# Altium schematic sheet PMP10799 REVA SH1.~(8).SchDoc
size 431 x 279 mm; Date: Not shown in title block; ApprovedBy: Not shown in title block; CheckedBy: Not shown in title block; Author: Not shown in title block; CompanyName: Not shown in title block; Engineer: Not shown in title block; Organization: Not shown in title block; Address1: Not shown in title block; Address2: Not shown in title block; Address3: Not shown in title block; Address4: Not shown in title block; DocumentNumber: 1; Revision: Use project parameter SCH_Rev; SheetNumber: 1; SheetTotal: 2; PageSetup: Record=PageOptions¦CenterHorizontal=True¦CenterVertical=True¦PrintScale=1.00¦XCorrection=1.00¦YCorrection=1.00¦PrintKind=0¦BorderSize=5000000¦LeftOffset=0¦BottomOffset=0¦Orientation=2¦PaperLength=1000¦PaperWidth=1000¦Scale=100¦PaperSource=15¦PrintQuality=600¦MediaType=1¦DitherType=10¦PaperKind=Letter¦PrintScaleMode=1
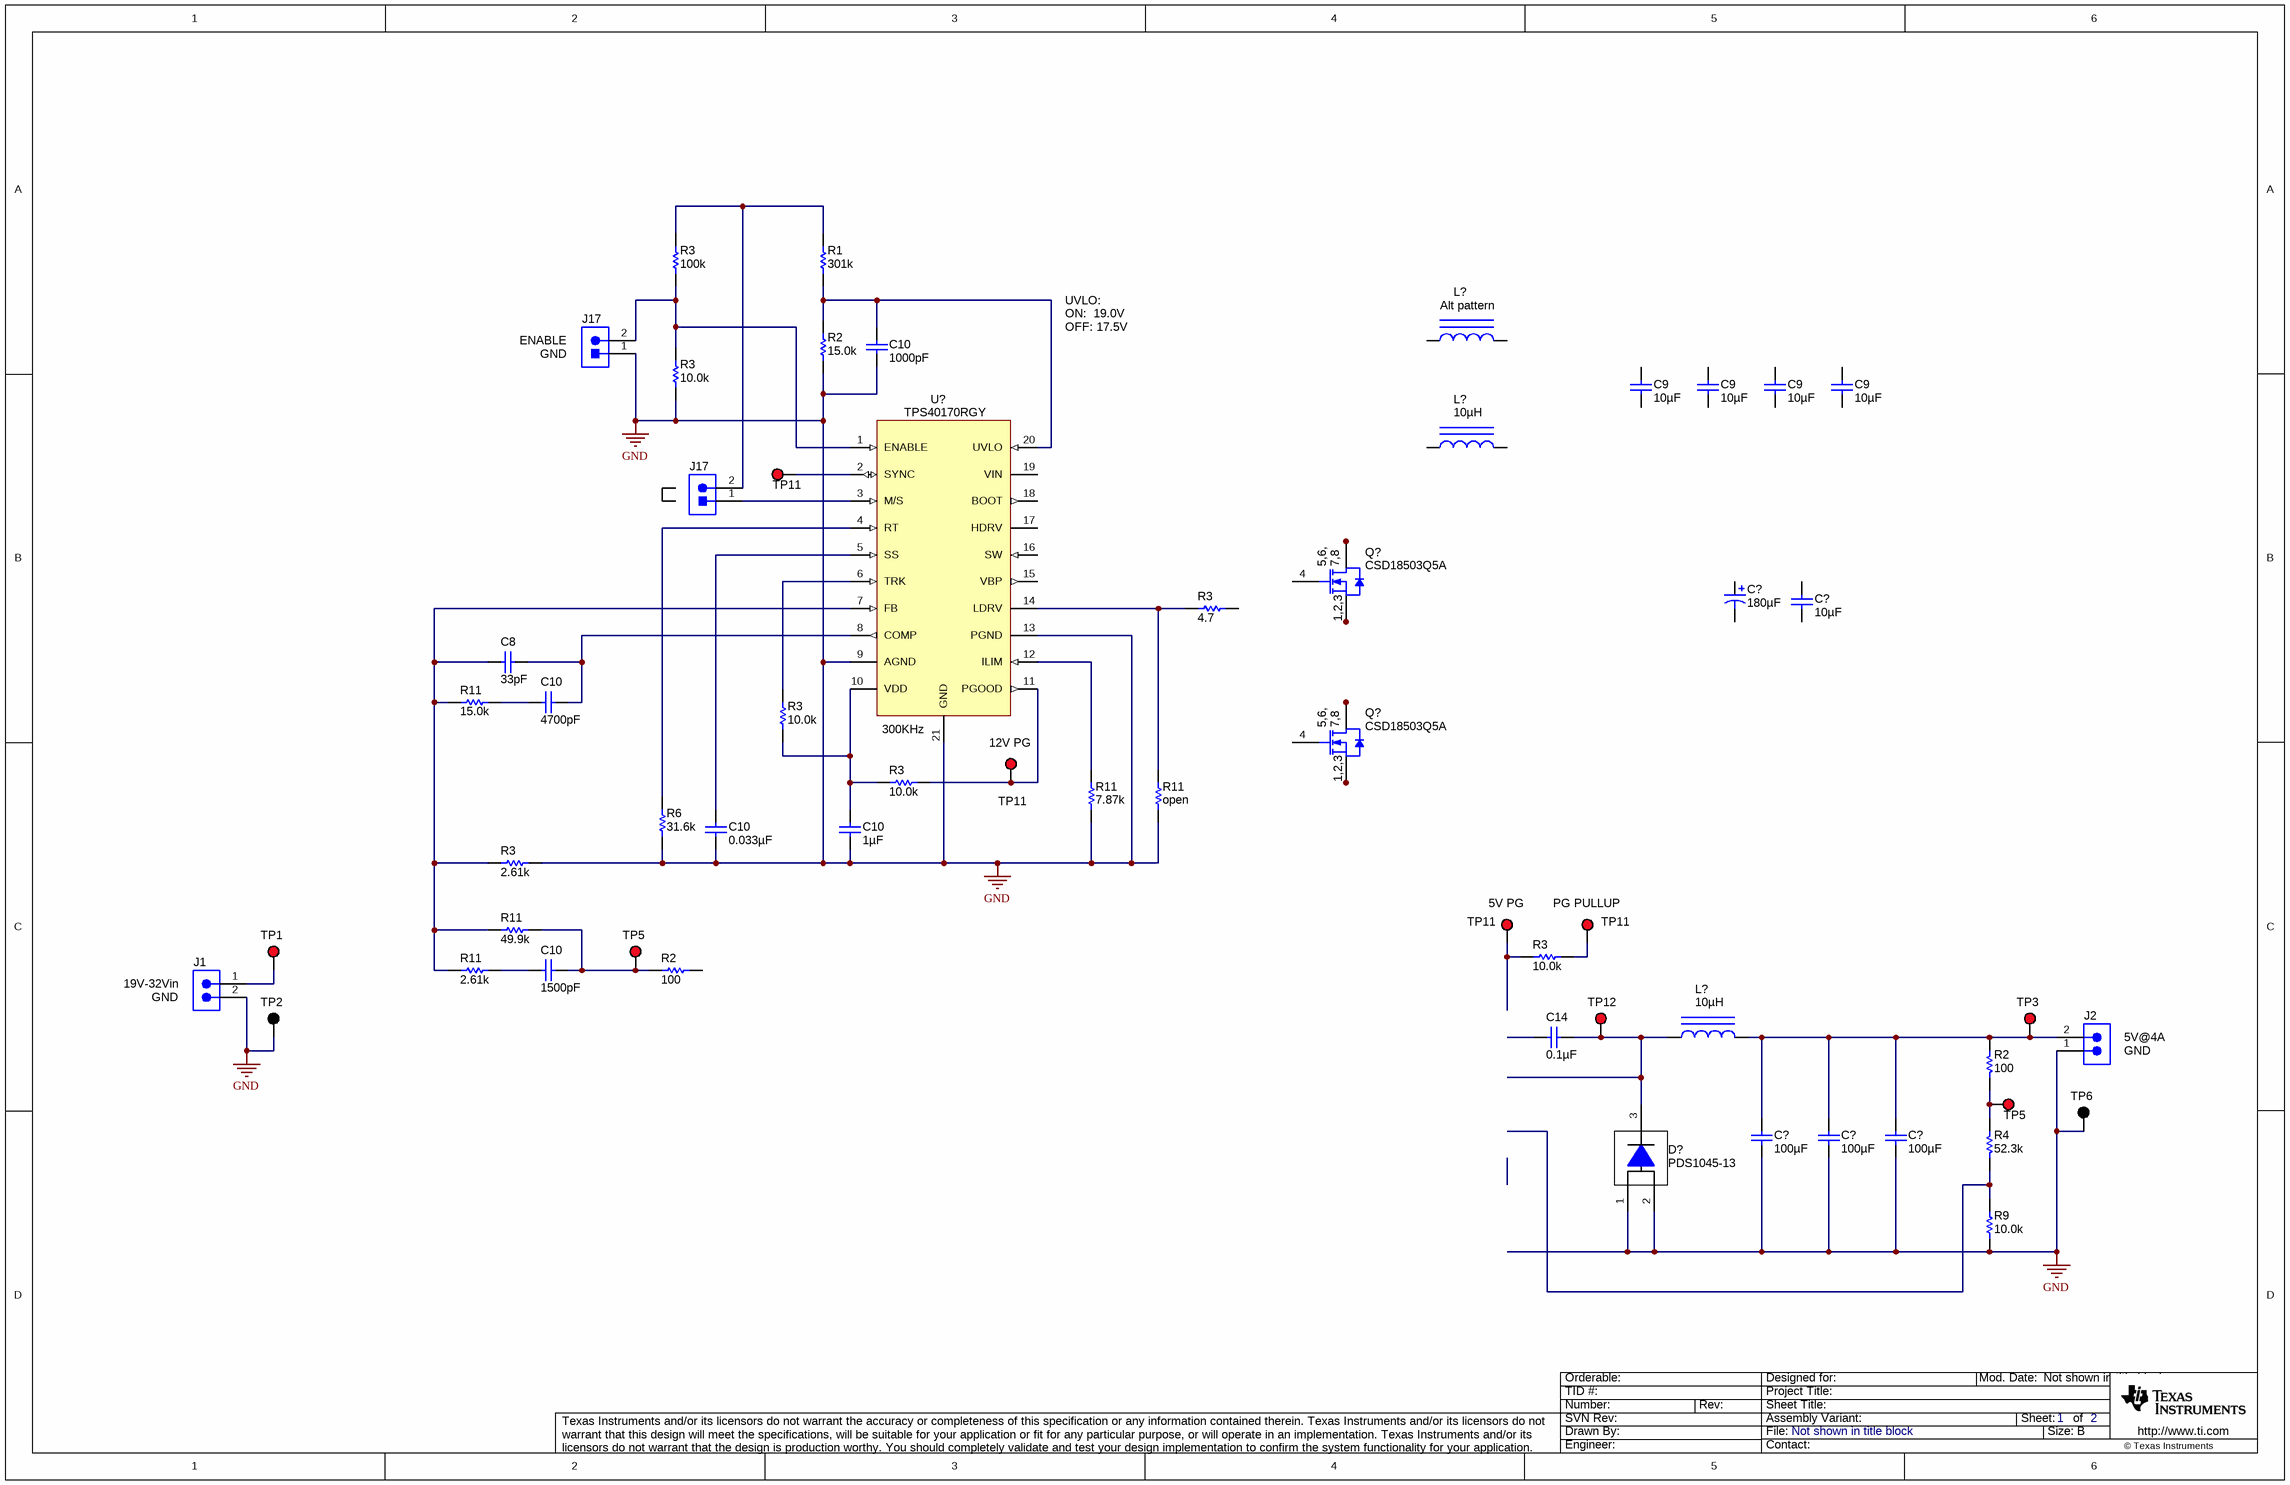
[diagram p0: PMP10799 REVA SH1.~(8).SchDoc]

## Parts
(Parts that share a designator on the sheet are numbered #1, #2 ... from top to bottom, then left to right.)
C8  ValueDisplayed: 33pF  [0603]  (hidden comment: C1608C0G1H330J)
C9#1  ValueDisplayed: 10µF  [1210]  (hidden comment: GRM32ER61H106MA12)
C9#2  ValueDisplayed: 10µF  [1210]  (hidden comment: GRM32ER61H106MA12)
C9#3  ValueDisplayed: 10µF  [1210]  (hidden comment: GRM32ER61H106MA12)
C9#4  ValueDisplayed: 10µF  [1210]  (hidden comment: GRM32ER61H106MA12)
C10#1  ValueDisplayed: 1000pF  [0603]  (hidden comment: C1608X7R1H102K)
C10#2  ValueDisplayed: 4700pF  [0603]  (hidden comment: C1608C0G1E472J)
C10#3  ValueDisplayed: 0.033µF  [0603]  (hidden comment: C1608X7R1H333K)
C10#4  ValueDisplayed: 1µF  [0603]  (hidden comment: C1608X5R1C105K)
C10#5  ValueDisplayed: 1500pF  [0603]  (hidden comment: C1608C0G1H152J)
C14  ValueDisplayed: 0.1µF  [0603]  (hidden comment: C1608X7R1H104K)
C?#1  ValueDisplayed: 180µF  [SM_RADIAL_6.3AMM]  (hidden comment: 16SVPF180M)
C?#2  ValueDisplayed: 10µF  [1206]  (hidden comment: GRM31CR71C106MAC7)
C?#3  ValueDisplayed: 100µF  [1210]  (hidden comment: GRM32EC80J107ME20)
C?#4  ValueDisplayed: 100µF  [1210]  (hidden comment: GRM32EC80J107ME20)
C?#5  ValueDisplayed: 100µF  [1210]  (hidden comment: GRM32EC80J107ME20)
D?  PDS1045-13  [PowerDI5]
J1  ED555/2DS  [TERM_BLK_ED555-2DS]  (value not drawn)
J2  ED555/2DS  [TERM_BLK_ED555-2DS]  (value not drawn)
J17#1  PEC02SAAN  [CONN_PEC02SAAN]  (value not drawn)
J17#2  PEC02SAAN  [CONN_PEC02SAAN]  (value not drawn)
L?#1  ValueDisplayed: Alt pattern  [XAL1510]  (hidden comment: XAL1510)
L?#2  ValueDisplayed: 10µH  [IND_MSS1210]  (hidden comment: MSS1210-103ME)
L?#3  ValueDisplayed: 10µH  [XAL8080_656]  (hidden comment: XAL8080-103ME)
Q?#1  CSD18503Q5A  [TRANS_NexFET_Q5A]
Q?#2  CSD18503Q5A  [TRANS_NexFET_Q5A]
R1  ValueDisplayed: 301k  [0603]  (hidden comment: CRCW0603301KFKEA)
R2#1  ValueDisplayed: 15.0k  [0603]  (hidden comment: CRCW060315K0FKEA)
R2#2  ValueDisplayed: 100  [0603L]  (hidden comment: CRCW0603100RFKEA)
R2#3  ValueDisplayed: 100  [0603L]  (hidden comment: CRCW0603100RFKEA)
R3#1  ValueDisplayed: 100k  [0603]  (hidden comment: CRCW0603100KFKEA)
R3#2  ValueDisplayed: 10.0k  [0603]  (hidden comment: CRCW060310K0FKEA)
R3#3  ValueDisplayed: 4.7  [0603]  (hidden comment: CRCW06034R70JNEA)
R3#4  ValueDisplayed: 10.0k  [0603]  (hidden comment: CRCW060310K0FKEA)
R3#5  ValueDisplayed: 10.0k  [0603]  (hidden comment: CRCW060310K0FKEA)
R3#6  ValueDisplayed: 2.61k  [0603]  (hidden comment: CRCW06032K61FKEA)
R3#7  ValueDisplayed: 10.0k  [0603]  (hidden comment: CRCW060310K0FKEA)
R4  ValueDisplayed: 52.3k  [0603L]  (hidden comment: CRCW060352K3FKEA)
R6  ValueDisplayed: 31.6k  [0603]  (hidden comment: CRCW060331K6FKEA)
R9  ValueDisplayed: 10.0k  [0603L]  (hidden comment: CRCW060310K0FKEA)
R11#1  ValueDisplayed: 15.0k  [0603]  (hidden comment: CRCW060315K0FKEA)
R11#2  ValueDisplayed: 7.87k  [0603]  (hidden comment: CRCW06037K87FKEA)
R11#3  ValueDisplayed: open  [0603]
R11#4  ValueDisplayed: 49.9k  [0603]  (hidden comment: CRCW060349K9FKEA)
R11#5  ValueDisplayed: 2.61k  [0603]  (hidden comment: CRCW06032K61FKEA)
TP1  5000  [Keystone5000]  (value not drawn)
TP2  5001  [Keystone5001]  (value not drawn)
TP3  5000  [Keystone5000]  (value not drawn)
TP5#1  5000  [Keystone5000]  (value not drawn)
TP5#2  5000  [Keystone5000]  (value not drawn)
TP6  5001  [Keystone5001]  (value not drawn)
TP11#1  5000  [Keystone5000]  (value not drawn)
TP11#2  5000  [Keystone5000]  (value not drawn)
TP11#3  5000  [Keystone5000]  (value not drawn)
TP11#4  5000  [Keystone5000]  (value not drawn)
TP12  5000  [Keystone5000]  (value not drawn)
U?  TPS40170RGY  [RGY0020A]

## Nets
GND: C10#1.2 C10#3.2 C10#4.2 C?#3.2 C?#4.2 C?#5.2 D?.1(A) D?.2(A) J1.2 J2.1 J17#1.1 R2#1.1 R3#2.2 R3#6.2 R6.1 R9.1 R11#2.1 R11#3.1 TP2.1 TP6.1 U?.9(AGND) U?.13(PGND) U?.21(GND)
NetC8_1: C8.1 R3#6.1 R11#1.2 R11#4.2 R11#5.2 U?.7(FB)
NetC8_2: C8.2 C10#2.2 U?.8(COMP)
NetC10#1_1: C10#1.1 R1.1 R2#1.2 U?.20(UVLO)
NetC10#2_1: C10#2.1 R11#1.1
NetC10#3_1: C10#3.1 U?.5(SS)
NetC10#4_1: C10#4.1 R3#4.2 R3#5.2 U?.10(VDD)
NetC10#5_1: C10#5.1 R11#5.1
NetC10#5_2: C10#5.2 R2#2.1 R11#4.1 TP5#1.1
NetC14_2: C14.2 D?.3(K) L?#3.1 TP12.1
NetC?#3_1: C?#3.1 C?#4.1 C?#5.1 J2.2 L?#3.2 R2#3.2 TP3.1
NetJ1_1: J1.1 TP1.1
NetJ17#1_2: J17#1.2 R3#1.2 R3#2.1 U?.1(ENABLE)
NetJ17#2_1: J17#2.1 U?.3(M/S)
NetJ17#2_2: J17#2.2 R1.2 R3#1.1
NetQ?#1_1: Q?#1.1(S) Q?#1.2(S) Q?#1.3(S)
NetQ?#1_5: Q?#1.5(D) Q?#1.6(D) Q?#1.7(D) Q?#1.8(D) Q?#1.9(D)
NetQ?#2_1: Q?#2.1(S) Q?#2.2(S) Q?#2.3(S)
NetQ?#2_5: Q?#2.5(D) Q?#2.6(D) Q?#2.7(D) Q?#2.8(D) Q?#2.9(D)
NetR2#3_1: R2#3.1 R4.2 TP5#2.1
NetR3#3_2: R3#3.2 R11#3.2 U?.14(LDRV)
NetR3#4_1: R3#4.1 U?.6(TRK)
NetR3#5_1: R3#5.1 TP11#2.1 U?.11(PGOOD)
NetR3#7_1: R3#7.1 TP11#4.1
NetR3#7_2: R3#7.2 TP11#3.1
NetR4_1: R4.1 R9.2
NetR6_2: R6.2 U?.4(RT)
NetR11#2_2: R11#2.2 U?.12(ILIM)
NetTP11#1_1: TP11#1.1 U?.2(SYNC)

Not connected (* = marked no-connect by the designer): C9#1 1 2; C9#2 1 2; C9#3 1 2; C9#4 1 2; C14 1; C?#1 1(+) 2(-); C?#2 1 2; L?#1 1 2; L?#2 1 2; Q?#1 4(G); Q?#2 4(G); R2#2 2; R3#3 1; U? 15(VBP) 16(SW) 17(HDRV) 18(BOOT) 19(VIN)

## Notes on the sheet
- UVLO:
- (near J17#1) ENABLE
- (near J17#1) GND
- OFF: 17.5V
- ON:  19.0V
- (near U?) 300KHz
- 12V PG
- (near TP11#3) 5V PG
- (near TP11#4) PG PULLUP
- (near J1) 19V-32Vin
- (near J1) GND
- (near J2) 5V@4A
- (near J2) GND

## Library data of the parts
C8 = C1608C0G1H330J: CAP, CERM, 33 pF, 50 V, +/- 5%, C0G/NP0, 0603; Manufacturer: TDK; Polarized: N; CompType: Capacitor; Value: 33pF; U/M: EA; Cap_F: 0.000000000033; Tolerance_%: 5; ESR_ohm: 0.2649; Value1: 0.2649 ohm; VDC_V: 50; Value2: 50V; TaMin_C: -55; TaMax_C: 125
C9#1-C9#4 = C3225X7R1E106M: CAP, CERM, 10uF, 50V, +/-20%, X5R, 1210; Manufacturer: MuRata; Polarized: N; CompType: Capacitor; U/M: EA; Cap_F: 0.00001; Tolerance_%: 20; ESR_Ohm: 0.0027; Value1: 0.0027 ohm; VDC_V: 50; IRMS_A: 3; TaMin_C: -55; TaMax_C: 125
C10#1 = C1608X7R1H102K: CAP, CERM, 1000 pF, 50 V, +/- 10%, X7R, 0603; Manufacturer: TDK; Polarized: N; CompType: Capacitor; Value: 1000pF; U/M: EA; Cap_F: 0.000000001; Tolerance_%: 10; ESR_ohm: 0.24; Value1: 0.24 ohm; VDC_V: 50; Value2: 50V; TaMin_C: -55; TaMax_C: 125
C10#2 = C1608C0G1E472J: CAP, CERM, 4700 pF, 25 V, +/- 5%, C0G/NP0, 0603; Manufacturer: TDK; Polarized: N; CompType: Capacitor; Value: 4700pF; U/M: EA; Cap_F: 0.0000000047; Tolerance_%: 5; Value1: Unknown; VDC_V: 25; Value2: 25V; TaMin_C: -55; TaMax_C: 125
C10#3 = C1608X7R1H473K: CAP, CERM, 0.033 µF, 50 V, +/- 10%, X7R, 0603; Manufacturer: TDK; Polarized: N; CompType: Capacitor; Value: 0.033uF; U/M: EA; Cap_F: 0.000000047; Tolerance_%: 10; ESR_ohm: 0.0234; Value1: 0.0234 ohm; VDC_V: 50; Value2: 50V; TaMin_C: -55; TaMax_C: 125
C10#4 = C1608X5R1C105K: CAP, CERM, 1 µF, 16 V, +/- 10%, X5R, 0603; Manufacturer: TDK; Polarized: N; CompType: Capacitor; Value: 1uF; U/M: EA; Cap_F: 0.000001; Tolerance_%: 10; ESR_ohm: 0.0057; Value1: 0.0057 ohm; VDC_V: 16; Value2: 16V; TaMin_C: -55; TaMax_C: 85
C10#5 = C1608C0G1H152J: CAP, CERM, 1500 pF, 50 V, +/- 5%, C0G/NP0, 0603; Manufacturer: TDK; Polarized: N; CompType: Capacitor; Value: 1500pF; U/M: EA; Cap_F: 0.0000000015; Tolerance_%: 5; ESR_ohm: 0.039; Value1: 0.039 ohm; VDC_V: 50; Value2: 50V; TaMin_C: -55; TaMax_C: 125
C14 = C1608X7R1H104K: CAP, CERM, 0.1uF, 50V, +/-10%, X7R, 0603; Manufacturer: TDK; Polarized: N; CompType: Capacitor; U/M: EA; Cap_F: 0.0000001; Tolerance_%: 10; ESR_Ohm: 0.017; Value1: 0.017 ohm; VDC_V: 50; TaMin_C: -55; TaMax_C: 125
C?#1 = 16SVP39M: CAP, OS-CON, 180 µF, 16 V, +/- 20%, 0.022 ohm, 6.3x5.9 SMD; Manufacturer: Sanyo; Polarized: Y; CompType: Capacitor; Value: 180uF; U/M: EA; Cap_F: 0.000039; Tolerance_%: 20; VDC_V: 16; Value2: 16V; ESR_ohm: 0.05; IRMS_A: 1.62; TaMin_C: -55; TaMax_C: 105; Cap_Case: 6.6x6.6x5.9
C?#2 = GRM31CR71C106KAC7L: CAP, CERM, 10 µF, 16 V, +/- 20%, X7R, 1206; Manufacturer: MuRata; Polarized: N; CompType: Capacitor; Value: 10uF; U/M: EA; Cap_F: 0.00001; Tolerance_%: 10; Value1: Unknown; VDC_V: 16; Value2: 16V; TaMin_C: -55; TaMax_C: 125
C?#3-C?#5 = C3225X5R0J107M: CAP, CERM, 100 µF, 6.3 V, +/- 20%, X6S, 1210; Manufacturer: MuRata; Polarized: N; CompType: Capacitor; Value: 100uF; U/M: EA; Cap_F: 0.0001; Tolerance_%: 20; ESR_ohm: 0.002; Value1: 0.002 ohm; VDC_V: 6.3; Value2: 6.3V; IRMS_A: 3.5; TaMin_C: -55; TaMax_C: 85
D? = PDS1045-13: Diode, Schottky, 45 V, 10 A, PowerDI5; Manufacturer: Diodes Inc.; SymbolCreator: a0412235; U/M: EA; Vf_V: 0.51; Value: 45V; Value1: 10A; Value2: 0.51V; Io_A: 10; Vr_V: 45; TJmax_C: 150; RJC_CperW: 85
J1 J2 = ED555/2DS: Terminal Block, 6A, 3.5mm Pitch, 2-Pos, TH; Manufacturer: On-Shore Technology, Inc.; SymbolCreator: a0412235; CompType: Connector; U/M: EA
J17#1 J17#2 = PEC02SAAN: Header, 100mil, 2x1, Tin, TH; Manufacturer: Sullins Connector Solutions; SymbolCreator: a0412235; U/M: EA
L?#1 = XAL1510-103MEB: Inductor, open, SMD; Manufacturer: Coilcraft; Ind_H: 10.0E-6; Imax_A: 22; Irms: 22A @ 40C rise; Isat: 26.3A @ 30% inductance drop; DCR_ohm: 0.0068; Material: Composite
L?#2 = MSS1210-103ME: Inductor, Shielded, Ferrite, 10 µH, 10 A, 0.014 ohm, SMD; Manufacturer: Coilcraft; Value: 10uH; Ind_H: 10.0E-6; Imax_A: 10; Irms: 10A @ 40C rise; Isat: 12.5A @ 30% inductance drop; DCR_ohm: 0.014; Value2: 10A
L?#3 = XAL8080-472ME: Inductor, Shielded, Composite, 10 µH, 8.7 A, 0.021 ohm, SMD; Manufacturer: Coilcraft; Value: 10uH; Ind_H: 10E-6; Imax_A: 8.7; Irms: 6.6A @ 20C rise; Isat: 10.9A @ 20% inductance drop; DCR_ohm: 21; Value2: 8.7A
Q?#1 Q?#2 = CSD18501Q5A: MOSFET, N-CH, 40 V, 3.4 milliohm, SON 5x6mm; Manufacturer: Texas Instruments; Alternate Manufacturer: None; U/M: EA; ChType: N; Value: 40V; VdsMax_V: 40; Value1: 0.0034 ohm; Rdson45_ohm: 0.0043; Value2: 13 nC; QgTyp_nC: 20; IdsMax_A: 22
R1 = CRCW0603301KFKEA: RES, 301 k, 1%, 0.1 W, 0603; Manufacturer: Vishay-Dale; CompType: Resistor; Value: 301k; Res_ohm: 301000; Tolerance_%: 1; Power_W: 0.1; Value2: 0.1W; VDC_V: 75; TempCo: 100 ppm/C; EIA_Code: E96; U/M: EA
R2#1 R11#1 = CRCW060315K0FKEA: RES, 15.0 k, 1%, 0.1 W, 0603; Manufacturer: Vishay-Dale; CompType: Resistor; Value: 15.0k; Res_ohm: 15000; Value_Code: 15k0; Tolerance_%: 1; Power_W: 0.1; Value2: 0.1W; VDC_V: 75; TempCo: 100 ppm/C; EIA_Code: E96; U/M: EA
R2#2 R2#3 = CRCW0603100RFKEA: RES, 100, 1%, 0.1 W, 0603; Manufacturer: Vishay-Dale; CompType: Resistor; Value: 100; Value_Code: 100R; Tolerance_%: 1; Power_W: 0.1; Value2: 0.1W; VDC_V: 75; TempCo: 100 ppm/C; EIA_Code: E96; U/M: EA
R3#1 = CRCW0603100KFKEA: RES, 100 k, 1%, 0.1 W, 0603; Manufacturer: Vishay-Dale; CompType: Resistor; Value: 100k; Res_ohm: 100000; Tolerance_%: 1; Power_W: 0.1; Value2: 0.1W; VDC_V: 75; TempCo: 100 ppm/C; EIA_Code: E96; U/M: EA
R3#2 R3#4 R3#5 R3#7 R9 = CRCW060310K0FKEA: RES, 10.0 k, 1%, 0.1 W, 0603; Manufacturer: Vishay-Dale; CompType: Resistor; Value: 10.0k; Res_ohm: 10000; Value_Code: 10k0; Tolerance_%: 1; Power_W: 0.1; Value2: 0.1W; VDC_V: 75; TempCo: 100 ppm/C; EIA_Code: E96; U/M: EA
R3#3 = CRCW06034R70JNEA: RES, 4.7, 5%, 0.1 W, 0603; Manufacturer: Vishay-Dale; CompType: Resistor; Value: 4.7; Value_Code: 4R70; Tolerance_%: 5; Power_W: 0.1; Value2: 0.1W; VDC_V: 75; TempCo: 200 ppm/C; EIA_Code: E24; U/M: EA
R3#6 R11#5 = CRCW06032K61FKEA: RES, 2.61 k, 1%, 0.1 W, 0603; Manufacturer: Vishay-Dale; CompType: Resistor; Value: 2.61k; Res_ohm: 2610; Value_Code: 2k61; Tolerance_%: 1; Power_W: 0.1; Value2: 0.1W; VDC_V: 75; TempCo: 100 ppm/C; EIA_Code: E96; U/M: EA
R4 = CRCW060352K3FKEA: RES, 52.3 k, 1%, 0.1 W, 0603; Manufacturer: Vishay-Dale; CompType: Resistor; Value: 52.3k; Res_ohm: 52300; Value_Code: 52k3; Tolerance_%: 1; Power_W: 0.1; Value2: 0.1W; VDC_V: 75; TempCo: 100 ppm/C; EIA_Code: E96; U/M: EA
R6 = CRCW060331K6FKEA: RES, 31.6 k, 1%, 0.1 W, 0603; Manufacturer: Vishay-Dale; CompType: Resistor; Value: 31.6k; Res_ohm: 31600; Value_Code: 31k6; Tolerance_%: 1; Power_W: 0.1; Value2: 0.1W; VDC_V: 75; TempCo: 100 ppm/C; EIA_Code: E96; U/M: EA
R11#2 = CRCW06037K87FKEA: RES, 7.87 k, 1%, 0.1 W, 0603; Manufacturer: Vishay-Dale; CompType: Resistor; Value: 7.87k; Res_ohm: 7870; Value_Code: 7k87; Tolerance_%: 1; Power_W: 0.1; Value2: 0.1W; VDC_V: 75; TempCo: 100 ppm/C; EIA_Code: E96; U/M: EA
R11#3 = CRCW06037K87FKEA: RES, open, 0603; CompType: Resistor; Tolerance_%: 1; Value1: 1%; Power_W: 0.1; Value2: 0.1W; TempCo: 100 ppm/C; EIA_Code: E96; U/M: EA
R11#4 = CRCW060349K9FKEA: RES, 49.9 k, 1%, 0.1 W, 0603; Manufacturer: Vishay-Dale; CompType: Resistor; Value: 49.9k; Res_ohm: 49900; Value_Code: 49k9; Tolerance_%: 1; Power_W: 0.1; Value2: 0.1W; VDC_V: 75; TempCo: 100 ppm/C; EIA_Code: E96; U/M: EA
TP1 TP3 TP5#1 TP5#2 TP11#1-TP11#4 TP12 = 5000: Test Point, TH, Miniature, Red; Manufacturer: Keystone; CompType: Test Point Loop; U/M: EA
TP2 TP6 = 5001: Test Point, TH, Miniature, Black; Manufacturer: Keystone; CompType: Test Point Loop; U/M: EA
U? = TPS40170RGY: 4.5-v to 60-v wide-input synchronous PWM buck controller, RGY0020A; Alternate Manufacturer: None; Manufacturer: Texas Instruments; SymbolCreator: a0412235/PADS; CompType: IC; U/M: EA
